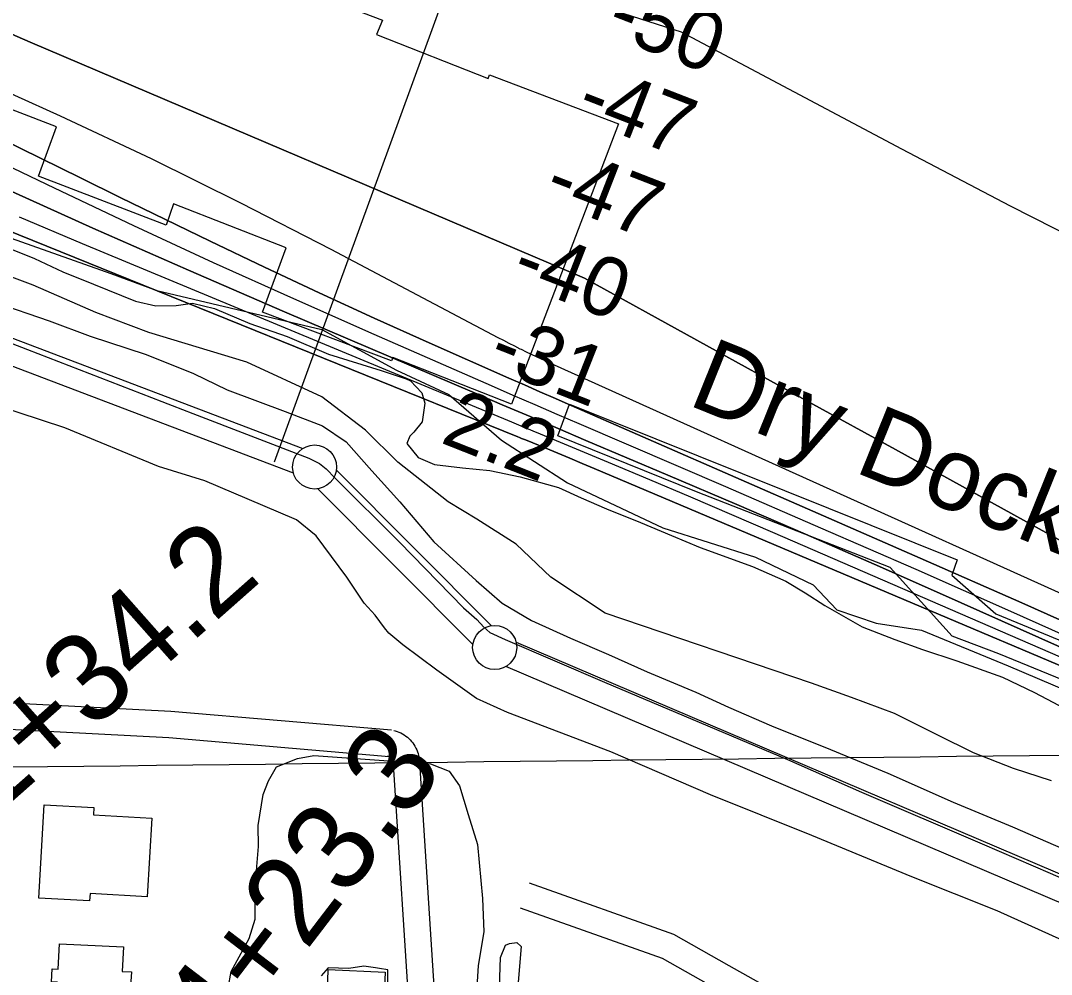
# Model space of a CAD drawing. Extents: x 3677843 to 3715951, y 511991 to 537744.
# Drawn here: x 3692904 to 3694073, y 529414 to 530495 of the extents above; entities that cross this region are included whole.
import ezdxf

# ---------------------------------------------------------------- set-up
doc = ezdxf.new("R2010")
doc.units = 0
for name, color, linetype in [('V-BLDG-OTLN', 7, 'Continuous'), ('V-CHAN-DOCK', 7, 'Continuous'), ('V-CHAN-DOCK-IDEN', 7, 'Continuous'), ('V-FLOD-BASE', 7, 'Continuous'), ('V-GRID-MAJR', 7, 'Continuous'), ('V-LEVE-TOET', 7, 'Continuous'), ('V-RIVR-EDGE', 7, 'Continuous'), ('V-RIVR-RANG', 7, 'Continuous'), ('V-ROAD-CNTR', 7, 'Continuous'), ('V-RRAP-RVMT', 7, 'Continuous'), ('V-SITE-VEGE', 7, 'Continuous'), ('V-SURV-IDEN', 7, 'Continuous'), ('V-SURV-LINE', 7, 'Continuous'), ('V-TOPO-DPTH', 7, 'Continuous'), ('V-TOPO-MAJR', 7, 'Continuous'), ('V-TOPO-MINR', 7, 'Continuous'), ('V-TOPO-WATR', 7, 'Continuous')]:
    doc.layers.add(name, color=color, linetype=linetype)

msp = doc.modelspace()

# ---------------------------------------------------------------- linework, layer by layer
at = {"layer": 'V-BLDG-OTLN'}
for points in [[(3693052.8370000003, 529590.949), (3693047.752, 529501.67), (3692982.892, 529505.365), (3692982.409, 529496.872), (3692924.794, 529500.153), (3692930.826, 529606.061), (3692987.199, 529602.85), (3692986.734, 529594.713)], [(3692948.127, 529448.314), (3693020.733, 529444.74), (3693019.369, 529417.047), (3693029.748, 529416.535), (3693028.9450000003, 529400.227), (3693019.7600000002, 529400.679), (3693018.4960000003, 529375.018), (3692944.826, 529378.643), (3692946.12, 529404.933), (3692939.1920000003, 529405.277), (3692939.911, 529419.859), (3692946.7120000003, 529419.5210000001)], [(3693253.056, 529419.204), (3693317.67, 529416.2930000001), (3693314.985, 529356.643), (3693287.208, 529357.893), (3693284.2260000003, 529291.613), (3693300.826, 529290.868), (3693299.8510000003, 529269.224), (3693255.964, 529271.201), (3693256.933, 529292.721), (3693274.795, 529291.9180000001), (3693276.352, 529326.554), (3693273.931, 529326.6630000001), (3693274.49, 529339.149), (3693251.358, 529340.192), (3693252.251, 529360.01), (3693249.14, 529360.152), (3693250.1580000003, 529382.729), (3693236.84, 529383.329), (3693237.383, 529395.402), (3693251.954, 529394.746)]]:
    msp.add_lwpolyline(points, close=True, dxfattribs=at)
at = {"layer": 'V-CHAN-DOCK'}
msp.add_lwpolyline([(3694313.265, 529654.1950000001), (3694013.1040000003, 529777.253), (3693960.4080000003, 529797.225), (3693890.103, 529875.23), (3693670.2970000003, 529960.916), (3693513.34, 530024.416), (3693526.443, 530060.336), (3693966.143, 529883.61), (3693959.878, 529866.2490000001), (3694009.986, 529822.432), (3694362.288, 529677.014)], dxfattribs=at)
at = {"layer": 'V-FLOD-BASE'}
msp.add_lwpolyline([(3692564.561, 530225.593), (3692617.531, 530232.399), (3692622.6920000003, 530231.6900000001), (3692633.436, 530228.696), (3692704.3910000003, 530201.333), (3692876.578, 530136.008), (3693099.417, 530049.719), (3693230.958, 529999.179), (3693242.943, 529993.037), (3693250.5700000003, 529986.823), (3693260.646, 529976.292), (3693333.919, 529903.807), (3693406.435, 529829.332), (3693421.307, 529816.106), (3693429.3680000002, 529807.523), (3693436.204, 529801.297), (3693453.369, 529793.256), (3693566.254, 529745.186), (3693773.666, 529657.458), (3693857.453, 529620.399), (3693994.2800000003, 529561.628), (3694071.273, 529528.419), (3694164.227, 529487.947)], dxfattribs=at)
at = {"layer": 'V-GRID-MAJR'}
msp.add_spline([(3681966.5640000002, 529526.479), (3687244.413, 529585.207), (3692522.254, 529644.703), (3697800.0870000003, 529704.966), (3703077.91, 529765.996), (3708355.725, 529827.795), (3713633.5300000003, 529890.361), (3713633.531, 529890.361)], degree=3, dxfattribs=at)
at = {"layer": 'V-LEVE-TOET'}
for points in [[(3692874.416, 530175.935), (3692936.503, 530154.878), (3692983.0270000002, 530137.507), (3693046.427, 530116.47), (3693100.378, 530095.017), (3693138.245, 530076.716), (3693204.0700000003, 530052.042), (3693246.637, 530035.658), (3693273.204, 530017.699), (3693302.38, 529984.806), (3693334.218, 529949.593), (3693372.796, 529903.979), (3693420.537, 529860.353), (3693450.123, 529834.563), (3693483.286, 529814.871), (3693527.49, 529794.835), (3693570.617, 529776.358), (3693614.5500000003, 529756.843), (3693669.84, 529733.574), (3693706.639, 529716.569), (3693755.588, 529695.561), (3693822.5, 529668.537), (3693887.3030000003, 529642.005), (3693961.412, 529608.795), (3694028.865, 529580.9940000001), (3694106.134, 529547.308)], [(3693321.721, 529800.599), (3693316.583, 529806.638), (3693306.103, 529820.917), (3693293.793, 529834.642), (3693274.134, 529864.011), (3693239.213, 529910.998), (3693216.849, 529929.024), (3693178.7460000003, 529945.482), (3693112.87, 529973.308), (3693060.585, 529989.535), (3692954.251, 530033.255), (3692849.381, 530067.805), (3692770.0700000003, 530097.778), (3692680.494, 530128.897), (3692598.411, 530151.732), (3692564.096, 530161.419)], [(3694120.8200000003, 529436.147), (3694011.498, 529485.862), (3693914.447, 529524.2170000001), (3693801.23, 529571.241), (3693686.185, 529617.446), (3693573.468, 529666.055), (3693456.347, 529710.65), (3693420.879, 529726.627), (3693376.216, 529758.7390000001), (3693337.39, 529787.27), (3693321.721, 529800.599)]]:
    msp.add_lwpolyline(points, dxfattribs=at)
at = {"layer": 'V-RIVR-EDGE'}
msp.add_lwpolyline([(3692874.9523822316, 530254.9462659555), (3693006.308810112, 530208.3963085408), (3693058.4894061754, 530189.056828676), (3693245.681807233, 530144.7701114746), (3693330.2145284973, 530098.9362622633), (3693389.578218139, 530071.1744478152), (3693449.482853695, 530019.3982304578), (3693524.4044698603, 529971.1868402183), (3693632.3364268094, 529919.8921917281), (3693737.311301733, 529886.6146542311), (3693802.669314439, 529855.236057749), (3693829.6140797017, 529826.9540793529), (3693874.000868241, 529811.836157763), (3693925.6093454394, 529803.904298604), (3694023.9628546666, 529763.4392142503), (3694317.813829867, 529638.4449922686)], dxfattribs=at)
at = {"layer": 'V-RIVR-RANG'}
msp.add_line((3693191.9615, 529994.8079000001), (3693431.5539, 530652.5277999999), dxfattribs=at)
at = {"layer": 'V-ROAD-CNTR'}
for points in [[(3692660.343640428, 529733.8665060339), (3693074.3338124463, 529712.2425492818), (3693324.7063117, 529690.7995921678)], [(3692658.9726431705, 529703.8975659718), (3693072.2718165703, 529682.30860915), (3693322.1463168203, 529660.909651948)], [(3693327.220306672, 529690.366593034), (3693328.9633031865, 529689.9115939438), (3693331.095298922, 529689.217595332), (3693333.1832947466, 529688.400596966), (3693335.2242906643, 529687.4585988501), (3693337.203286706, 529686.400600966), (3693339.108282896, 529685.232603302), (3693340.947279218, 529683.9526058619), (3693342.717275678, 529682.5596086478), (3693344.394272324, 529681.06861163), (3693345.975269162, 529679.48861479), (3693347.4682661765, 529677.81361814), (3693348.860263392, 529676.04862167), (3693350.1432608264, 529674.2116253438), (3693351.315258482, 529672.3036291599), (3693352.37625636, 529670.3256331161), (3693353.318254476, 529668.2886371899), (3693354.138252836, 529666.2006413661), (3693354.834251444, 529664.0706456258), (3693355.4032503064, 529661.902649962), (3693355.8452494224, 529659.7016543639), (3693356.1572487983, 529657.479658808), (3693356.337248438, 529655.245663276), (3693356.3832483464, 529653.156667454), (3693356.37124837, 529652.4496688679)], [(3693319.632321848, 529661.3426510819), (3693320.52132007, 529661.109651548), (3693320.977319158, 529660.9616518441), (3693321.423318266, 529660.786652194), (3693321.854317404, 529660.5886525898), (3693322.275316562, 529660.3626530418), (3693322.6903157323, 529660.1086535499), (3693323.0853149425, 529659.8346540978), (3693323.453314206, 529659.54365468), (3693323.810313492, 529659.226655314), (3693324.155312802, 529658.8826560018), (3693324.472312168, 529658.5256567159), (3693324.7663115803, 529658.1546574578), (3693325.0413110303, 529657.7596582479), (3693325.293310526, 529657.3496590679), (3693325.5183100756, 529656.9296599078), (3693325.7183096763, 529656.496660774), (3693325.894309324, 529656.050661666), (3693326.042309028, 529655.5946625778), (3693326.1653087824, 529655.130663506), (3693326.259308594, 529654.661664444), (3693326.325308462, 529654.1896653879), (3693326.363308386, 529653.711666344), (3693326.3773083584, 529653.07866761), (3693326.3753083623, 529652.9576678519)], [(3693326.4043083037, 529651.740670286), (3693345.670269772, 529352.188269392), (3693342.1532768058, 529073.4488268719), (3693340.4062803, 529041.7718902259)], [(3693356.3422484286, 529653.6666664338), (3693375.6822097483, 529352.962267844), (3693372.1432168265, 529072.4328289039), (3693370.3682203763, 529040.267893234)], [(3694115.37973035, 529157.9936577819), (3694116.897727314, 529195.4035829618), (3694115.0347310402, 529211.1135515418), (3694111.257738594, 529223.6095265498), (3694105.0717509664, 529233.4555068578), (3694097.7527656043, 529246.18948139), (3694085.476790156, 529252.6484684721), (3693778.3524044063, 529383.695206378), (3693707.459546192, 529423.370127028), (3693644.5906719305, 529458.8900559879), (3693481.0029991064, 529516.980939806)], [(3693722.66051579, 529380.4842128), (3693692.7555756, 529397.220179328), (3693632.0986969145, 529431.4901107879), (3693470.963019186, 529488.710996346)]]:
    msp.add_lwpolyline(points, dxfattribs=at)
at = {"layer": 'V-RRAP-RVMT'}
for points in [[(3693077.6470000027, 530287.6120000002), (3693069.0260000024, 530263.2570000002), (3692924.3570000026, 530318.6790000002), (3692944.7520000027, 530374.7690000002), (3692806.1400000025, 530427.9400000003), (3692809.3070000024, 530436.8100000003), (3692677.5410000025, 530487.9920000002), (3692674.2020000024, 530479.9270000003), (3692406.6180000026, 530599.0320000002), (3692269.7520000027, 530659.9670000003), (3692269.3720000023, 530657.6340000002), (3692135.2830000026, 530717.6810000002), (3692127.5800000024, 530701.7640000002), (3691984.2100000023, 530764.5290000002), (3691987.2450000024, 530772.4760000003), (3691854.0790000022, 530831.8620000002)], [(3693165.5790000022, 530542.8450000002), (3693168.8920000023, 530551.1280000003), (3693314.3710000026, 530495.7870000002), (3693307.7140000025, 530479.5620000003), (3693434.3250000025, 530429.5830000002), (3693435.8330000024, 530433.7290000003), (3693581.8890000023, 530378.3220000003), (3693460.7230000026, 530060.4190000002), (3693326.2840000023, 530113.0140000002), (3693324.5690000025, 530109.5200000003), (3693178.3070000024, 530164.6040000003), (3693205.3750000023, 530237.4150000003), (3693077.6470000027, 530287.6120000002)]]:
    msp.add_lwpolyline(points, dxfattribs=at)
at = {"layer": 'V-SITE-VEGE'}
for points in [[(3692890.754, 530237.33), (3692919.967, 530225.368), (3692952.19, 530210.495), (3692986.771, 530196.256), (3693034.463, 530176.8960000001), (3693057.642, 530171.944), (3693080.7290000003, 530172.319), (3693099.044, 530174.987), (3693124.018, 530168.88), (3693163.974, 530151.767), (3693206.259, 530137.056), (3693253.369, 530117.098), (3693312.894, 530098.525), (3693341.4760000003, 530088.922)], [(3694072.821, 529632.996), (3694029.954, 529647.103), (3693984.661, 529664.724), (3693944.063, 529684.7880000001), (3693895.1, 529709.456), (3693846.2430000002, 529727.612), (3693800.968, 529744.047), (3693566.9390000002, 529823.143), (3693505.273, 529864.183), (3693466.173, 529901.448), (3693421.295, 529929.735), (3693388.9960000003, 529949.345), (3693331.998, 529994.608), (3693295.286, 530030.726), (3693245.517, 530068.409), (3693160.779, 530107.8910000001), (3693049.489, 530141.609), (3692989.304, 530164.3150000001), (3692918.329, 530195.14), (3692859.34, 530217.274)], [(3693341.4760000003, 530088.922), (3693346.252, 530086.632), (3693358.907, 530073.218), (3693362.653, 530061.434), (3693359.447, 530040.063), (3693350.1580000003, 530028.66), (3693345.501, 530023.8470000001), (3693342.08, 530015.4990000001), (3693354.776, 529999.715), (3693373.2630000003, 529991.728), (3693405.302, 529988.103), (3693436.145, 529985.054), (3693470.611, 529977.916), (3693514.043, 529965.596), (3693539.694, 529954.17), (3693568.325, 529941.607), (3693607.069, 529926.247), (3693642.252, 529911.424), (3693674.452, 529897.735), (3693734.025, 529876.2), (3693771.603, 529859.64), (3693793.73, 529846.379), (3693815.879, 529831.937), (3693858.3200000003, 529807.756), (3693895.272, 529793.553), (3693926.84, 529782.224), (3693965.5470000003, 529769.233), (3694017.3740000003, 529750.535), (3694053.7770000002, 529733.363), (3694129.643, 529693.142)], [(3693139.404, 529398.087), (3693142.98, 529416.768), (3693163.321, 529454.3470000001), (3693169.948, 529476.183), (3693170.2060000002, 529508.005), (3693172.078, 529535.97), (3693174.04, 529558.506), (3693173.647, 529582.556), (3693179.285, 529617.567), (3693185.238, 529633.185), (3693194.295, 529648.854), (3693218.193, 529658.555), (3693236.762, 529661.961), (3693368.835, 529652.475), (3693389.9220000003, 529644.281), (3693401.8370000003, 529627.403), (3693411.6780000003, 529594.971), (3693422.319, 529561.001), (3693427.974, 529499.7880000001), (3693429.3680000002, 529461.7880000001), (3693423.005, 529423.66), (3693410.0640000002, 529217.807)], [(3693320.656, 529392.729), (3693320.378, 529418.7490000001), (3693311.1580000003, 529420.18), (3693306.648, 529420.987), (3693293.4220000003, 529423.101), (3693276.393, 529420.4940000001), (3693252.958, 529420.957), (3693245.056, 529412.058)]]:
    msp.add_lwpolyline(points, dxfattribs=at)
msp.add_lwpolyline([(3693457.7490000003, 529277.943), (3693460.187, 529273.837), (3693454.8680000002, 529273.159), (3693448.345, 529273.644), (3693442.987, 529275.334), (3693448.1180000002, 529432.944), (3693453.815, 529446.657), (3693458.524, 529448.51), (3693466.793, 529449.829), (3693471.606, 529445.17)], close=True, dxfattribs=at)
at = {"layer": 'V-SURV-LINE'}
for points in [[(3692648.155193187, 530228.9588554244), (3693224.1633175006, 530010.1286212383)], [(3693213.498130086, 529982.08840167), (3692637.4904387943, 530200.9184713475)], [(3693262.230526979, 529985.4698835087), (3693438.213172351, 529809.0907934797)], [(3693416.9743354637, 529787.9032543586), (3693240.9925097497, 529964.2815228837)], [(3693465.958385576, 529790.326522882), (3695168.724882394, 529064.6919901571)], [(3695156.9827727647, 529037.0854096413), (3693454.2169142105, 529762.7196703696)]]:
    msp.add_lwpolyline(points, dxfattribs=at)
for centre in [(3693237.50456, 529989.01356), (3693441.70018, 529784.3586300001)]:
    msp.add_circle(centre, 25, dxfattribs=at)
at = {"layer": 'V-TOPO-DPTH'}
for points in [[(3694479.8169192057, 529595.7881891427), (3693554.3810636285, 529987.3874126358), (3693540.71876213, 529993.1447640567), (3693527.045173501, 529998.8750698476), (3693513.3546541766, 530004.5648071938), (3693499.652847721, 530010.2274989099), (3693476.7239945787, 530019.6637758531), (3693474.477304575, 530020.5859741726), (3693472.2294884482, 530021.5054121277), (3693469.979983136, 530022.4207095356), (3693467.7293517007, 530023.3332465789), (3692713.1121425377, 530328.4903390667), (3692684.1569764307, 530340.3346559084), (3692655.2665394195, 530352.333084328), (3692626.4731960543, 530364.5626801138), (3692597.7445817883, 530376.9463874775), (3692569.1407062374, 530389.6116163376), (3692540.638378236, 530402.4980029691), (3692512.2883715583, 530415.7161262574), (3692484.0399124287, 530429.1554073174), (3691755.1334836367, 530781.1652881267)], [(3694091.732278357, 529900.92663095), (3693993.840304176, 529954.8123030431), (3693895.971738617, 530008.7404788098), (3693798.1187788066, 530062.6969903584), (3693543.44, 530203.2), (3692915.0172293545, 530470.6403329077), (3692861.6383207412, 530493.96854862)], [(3694091.732278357, 529900.92663095), (3693993.840304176, 529954.8123030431), (3693895.971738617, 530008.7404788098), (3693798.1187788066, 530062.6969903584), (3693543.44, 530203.2), (3692915.0172293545, 530470.6403329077), (3692861.6383207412, 530493.96854862)], [(3692844.947129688, 530434.0414603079), (3692948.9348983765, 530387.106426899), (3693052.208311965, 530338.6895877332), (3693154.410192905, 530288.0500399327), (3693255.8977187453, 530235.9286863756), (3693445.400666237, 530135.9993599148), (3693451.610951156, 530132.7507212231), (3693457.835341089, 530129.5295603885), (3693464.0808885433, 530126.3496163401), (3693470.340541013, 530123.1971501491), (3693471.725840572, 530122.5052207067), (3693477.318037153, 530119.7499666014), (3693482.9297138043, 530117.0355504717), (3693488.5706105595, 530114.3823913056), (3693494.230987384, 530111.7700701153), (3693502.165775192, 530108.1603520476), (3693503.8737352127, 530107.3843281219), (3693505.5821792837, 530106.609372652), (3693507.2913494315, 530105.8360198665), (3693509.001003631, 530105.0637355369), (3694145.8307099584, 529817.7547701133)], [(3692844.947129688, 530434.0414603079), (3692948.9348983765, 530387.106426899), (3693052.208311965, 530338.6895877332), (3693154.410192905, 530288.0500399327), (3693255.8977187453, 530235.9286863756), (3693445.400666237, 530135.9993599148), (3693451.610951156, 530132.7507212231), (3693457.835341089, 530129.5295603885), (3693464.0808885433, 530126.3496163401), (3693470.340541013, 530123.1971501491), (3693471.725840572, 530122.5052207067), (3693477.318037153, 530119.7499666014), (3693482.9297138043, 530117.0355504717), (3693488.5706105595, 530114.3823913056), (3693494.230987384, 530111.7700701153), (3693502.165775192, 530108.1603520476), (3693503.8737352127, 530107.3843281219), (3693505.5821792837, 530106.609372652), (3693507.2913494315, 530105.8360198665), (3693509.001003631, 530105.0637355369), (3694145.8307099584, 529817.7547701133)], [(3692881.578814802, 530361.6239129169), (3692926.687718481, 530339.1081581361), (3692971.9048153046, 530316.8104775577), (3693017.194040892, 530294.6581797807), (3693118.9662627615, 530245.1825179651), (3693180.7575617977, 530215.5498836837), (3693242.754207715, 530186.3594881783), (3693305.0588739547, 530157.8324508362), (3693367.5688870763, 530129.7476522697), (3693457.682329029, 530089.8376770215), (3693475.2957831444, 530082.0535297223), (3693492.9173854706, 530074.287911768), (3693510.5512101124, 530066.5500878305), (3693528.193182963, 530058.8307932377), (3693808.565624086, 529936.4163088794), (3693923.922047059, 529885.7896964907), (3694039.1493104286, 529834.8722843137), (3694154.1828343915, 529783.5186724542)], [(3694154.1828343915, 529783.5186724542), (3694039.1493104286, 529834.8722843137), (3693923.922047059, 529885.7896964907), (3693808.565624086, 529936.4163088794), (3693528.193182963, 530058.8307932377), (3693510.5512101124, 530066.5500878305), (3693492.9173854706, 530074.287911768), (3693475.2957831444, 530082.0535297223), (3693457.682329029, 530089.8376770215), (3693367.5688870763, 530129.7476522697), (3693305.0588739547, 530157.8324508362), (3693242.754207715, 530186.3594881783), (3693180.7575617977, 530215.5498836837), (3693118.9662627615, 530245.1825179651), (3693017.194040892, 530294.6581797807), (3692971.9048153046, 530316.8104775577), (3692926.687718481, 530339.1081581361), (3692881.578814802, 530361.6239129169)], [(3694474.2775584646, 529610.2558987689), (3693949.28905558, 529844.582755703), (3693871.7199938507, 529878.9375211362), (3693794.020845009, 529912.9931446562), (3693716.126565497, 529946.6000553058), (3693638.1021988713, 529979.9078240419), (3693545.1808327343, 530019.2585401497), (3693513.5259301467, 530032.6815152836), (3693481.879499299, 530046.1244079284), (3693450.2457760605, 530059.5971768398), (3693418.620524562, 530073.0898632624), (3693203.244077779, 530165.0988958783), (3693094.5092651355, 530212.1564938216), (3692986.0769979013, 530259.8926488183), (3692878.0985487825, 530308.6466393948)], [(3692878.0985487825, 530308.6466393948), (3692986.0769979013, 530259.8926488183), (3693094.5092651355, 530212.1564938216), (3693203.244077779, 530165.0988958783), (3693418.620524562, 530073.0898632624), (3693450.2457760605, 530059.5971768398), (3693481.879499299, 530046.1244079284), (3693513.5259301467, 530032.6815152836), (3693545.1808327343, 530019.2585401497), (3693638.1021988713, 529979.9078240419), (3693716.126565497, 529946.6000553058), (3693794.020845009, 529912.9931446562), (3693871.7199938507, 529878.9375211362), (3693949.28905558, 529844.582755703), (3694474.2775584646, 529610.2558987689)]]:
    msp.add_lwpolyline(points, dxfattribs=at)
at = {"layer": 'V-TOPO-MAJR'}
msp.add_lwpolyline([(3691759.2825659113, 531014.3568125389), (3691875.807524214, 530984.7180011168), (3691992.4973998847, 530955.7562331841), (3692109.4346516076, 530927.8100304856), (3692226.5368206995, 530900.5408712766), (3692616.5783132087, 530811.4989914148), (3692632.770957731, 530807.5830035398), (3692648.8883408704, 530803.392112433), (3692664.8928319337, 530798.7888664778), (3692680.822061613, 530793.9107172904), (3693652.92, 530482.51), (3693902.755021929, 530349.7668273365), (3694026.257931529, 530285.2711107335), (3694150.3539094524, 530221.9585907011)], dxfattribs=at)
at = {"layer": 'V-TOPO-MINR'}
for points in [[(3692861.6383207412, 530493.96854862), (3692915.0172293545, 530470.6403329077), (3693543.44, 530203.2), (3693798.1187788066, 530062.6969903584), (3693895.971738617, 530008.7404788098), (3693993.840304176, 529954.8123030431), (3694091.732278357, 529900.92663095)], [(3692642.49823796, 530449.2007204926), (3692942.1851759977, 530305.5625137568), (3693032.2752353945, 530262.9576965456), (3693122.653139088, 530220.9811577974), (3693213.462809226, 530179.9470367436), (3693304.5603236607, 530139.5411941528), (3693437.5631977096, 530081.3744590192), (3693462.385348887, 530070.5466881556), (3693487.2210152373, 530059.7500867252), (3693512.0769543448, 530049.0002394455), (3693536.946408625, 530038.2815615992), (3693703.2725935, 529966.7808460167), (3693811.1996130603, 529920.0720579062), (3693918.9724229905, 529873.0124495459), (3694026.5139184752, 529825.4266108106), (3694133.90120433, 529777.4899518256)], [(3692844.947129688, 530434.0414603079), (3692948.9348983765, 530387.106426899), (3693052.208311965, 530338.6895877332), (3693154.410192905, 530288.0500399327), (3693255.8977187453, 530235.9286863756), (3693445.400666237, 530135.9993599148), (3693451.610951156, 530132.7507212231), (3693457.835341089, 530129.5295603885), (3693464.0808885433, 530126.3496163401), (3693470.340541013, 530123.1971501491), (3693471.725840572, 530122.5052207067), (3693477.318037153, 530119.7499666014), (3693482.9297138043, 530117.0355504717), (3693488.5706105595, 530114.3823913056), (3693494.230987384, 530111.7700701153), (3693502.165775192, 530108.1603520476), (3693503.8737352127, 530107.3843281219), (3693505.5821792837, 530106.609372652), (3693507.2913494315, 530105.8360198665), (3693509.001003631, 530105.0637355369), (3694145.8307099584, 529817.7547701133)], [(3692881.578814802, 530361.6239129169), (3692926.687718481, 530339.1081581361), (3692971.9048153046, 530316.8104775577), (3693017.194040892, 530294.6581797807), (3693118.9662627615, 530245.1825179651), (3693180.7575617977, 530215.5498836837), (3693242.754207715, 530186.3594881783), (3693305.0588739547, 530157.8324508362), (3693367.5688870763, 530129.7476522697), (3693457.682329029, 530089.8376770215), (3693475.2957831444, 530082.0535297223), (3693492.9173854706, 530074.287911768), (3693510.5512101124, 530066.5500878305), (3693528.193182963, 530058.8307932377), (3693808.565624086, 529936.4163088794), (3693923.922047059, 529885.7896964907), (3694039.1493104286, 529834.8722843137), (3694154.1828343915, 529783.5186724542)], [(3692878.0985487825, 530308.6466393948), (3692986.0769979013, 530259.8926488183), (3693094.5092651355, 530212.1564938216), (3693203.244077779, 530165.0988958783), (3693418.620524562, 530073.0898632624), (3693450.2457760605, 530059.5971768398), (3693481.879499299, 530046.1244079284), (3693513.5259301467, 530032.6815152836), (3693545.1808327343, 530019.2585401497), (3693638.1021988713, 529979.9078240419), (3693716.126565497, 529946.6000553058), (3693794.020845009, 529912.9931446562), (3693871.7199938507, 529878.9375211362), (3693949.28905558, 529844.582755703), (3694474.2775584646, 529610.2558987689)], [(3692902.496589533, 530272.6050698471), (3692973.983934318, 530242.5127501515), (3693460.6329757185, 530040.1304783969), (3693468.756209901, 530036.7504502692), (3693476.8785793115, 530033.3683464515), (3693484.999651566, 530029.9831290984), (3693493.1198590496, 530026.5958360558), (3693570.3532874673, 529994.3610198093), (3693617.049363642, 529974.760253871), (3693663.691845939, 529955.0334820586), (3693710.2539374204, 529935.1177014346), (3693756.762435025, 529915.0759149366), (3694477.0212038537, 529602.9633031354)]]:
    msp.add_lwpolyline(points, dxfattribs=at)
at = {"layer": 'V-TOPO-WATR'}
msp.add_lwpolyline([(3691755.1334836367, 530781.1652881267), (3692484.0399124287, 530429.1554073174), (3692512.2883715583, 530415.7161262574), (3692540.638378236, 530402.4980029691), (3692569.1407062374, 530389.6116163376), (3692597.7445817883, 530376.9463874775), (3692626.4731960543, 530364.5626801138), (3692655.2665394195, 530352.333084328), (3692684.1569764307, 530340.3346559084), (3692713.1121425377, 530328.4903390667), (3693467.7293517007, 530023.3332465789), (3693469.979983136, 530022.4207095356), (3693472.2294884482, 530021.5054121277), (3693474.477304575, 530020.5859741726), (3693476.7239945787, 530019.6637758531), (3693499.652847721, 530010.2274989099), (3693513.3546541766, 530004.5648071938), (3693527.045173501, 529998.8750698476), (3693540.71876213, 529993.1447640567), (3693554.3810636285, 529987.3874126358), (3694479.8169192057, 529595.7881891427)], dxfattribs=at)

# ---------------------------------------------------------------- texts
at = {"layer": 'V-CHAN-DOCK-IDEN'}
msp.add_text('Dry Dock', height=82.99983200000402, rotation=338.0394282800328, dxfattribs=at).set_placement((3693658.8396434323, 530060.164853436))
at = {"layer": 'V-RIVR-RANG'}
for s, height, rotation, p in [('-50', 67.00000000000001, 338.73886111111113, (3693565.0558466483, 530480.7537678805)), ('-47', 67.00000000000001, 338.73886111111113, (3693531.267932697, 530386.597601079)), ('-47', 67.00000000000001, 338.73886111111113, (3693494.7759326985, 530293.493601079)), ('-40', 67.00000000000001, 338.73886111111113, (3693457.5464546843, 530200.6765556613)), ('-31', 66.99999999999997, 338.4583257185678, (3693431.3470224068, 530103.9262834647)), ('2.2', 66.99999999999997, 338.4583257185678, (3693378.661610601, 530017.214647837))]:
    msp.add_text(s, height=height, rotation=rotation, dxfattribs=at).set_placement(p)
at = {"layer": 'V-SURV-IDEN'}
for s, rotation, p in [('131+34.2', 41.4992780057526, (3692758.680433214, 529489.2736744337)), ('134+23.3', 52.63324943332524, (3693044.9823087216, 529200.2201819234))]:
    msp.add_text(s, height=99.99999999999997, rotation=rotation, dxfattribs=at).set_placement(p)

doc.saveas('drawing.dxf')
